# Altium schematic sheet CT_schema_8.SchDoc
size 254 x 194 mm
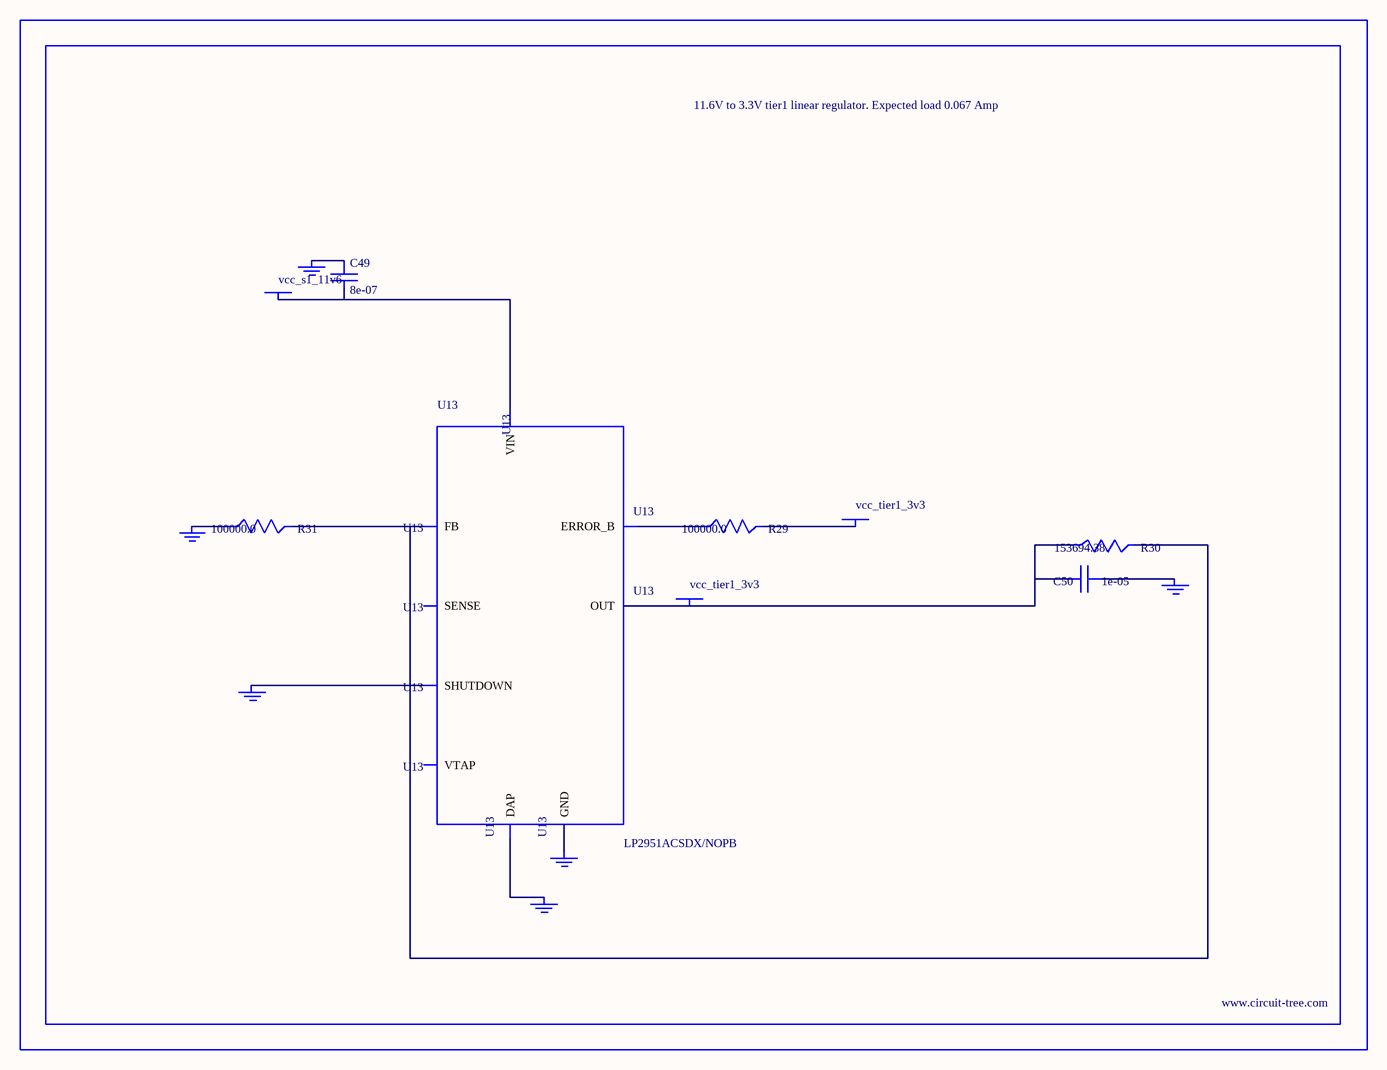
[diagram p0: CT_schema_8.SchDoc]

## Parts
BORDER7  (no value)
C49  8e-07  [R0603]
C50  1e-05  [C1210]
GND_INSTANCE_7_0  (no value)
GND_INSTANCE_7_1  (no value)
GND_INSTANCE_7_2  (no value)
GND_INSTANCE_7_3  (no value)
GND_INSTANCE_7_4  (no value)
GND_INSTANCE_7_5  (no value)
POWER_INSTANCE_7_0  vcc_tier1_3v3
POWER_INSTANCE_7_1  vcc_s1_11v6
POWER_INSTANCE_7_2  vcc_tier1_3v3
R29  100000.0  [R0603]
R30  153694.38  [R0603]
R31  100000.0  [R0603]
U13  LP2951ACSDX/NOPB  [WSON-8]

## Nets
NetC49_1: C49.1 GND_INSTANCE_7_3.0(GND)
NetC49_2: C49.2 POWER_INSTANCE_7_1.0(PWR) U13.8(VIN)
NetC50_1: C50.1 GND_INSTANCE_7_0.0(GND)
NetC50_2: C50.2 POWER_INSTANCE_7_2.0(PWR) R30.1 U13.1(OUT)
NetGND_INSTANCE_7_1_0: GND_INSTANCE_7_1.0(GND) U13.3(SHUTDOWN)
NetGND_INSTANCE_7_2_0: GND_INSTANCE_7_2.0(GND) R31.1
NetGND_INSTANCE_7_4_0: GND_INSTANCE_7_4.0(GND) U13.PAD(DAP)
NetGND_INSTANCE_7_5_0: GND_INSTANCE_7_5.0(GND) U13.4(GND)
NetPOWER_INSTANCE_7_0_0: POWER_INSTANCE_7_0.0(PWR) R29.2
NetR29_1: R29.1 U13.5(ERROR_B)
NetR30_2: R30.2 R31.2 U13.7(FB)

Not connected (* = marked no-connect by the designer): U13 2(SENSE) 6(VTAP)

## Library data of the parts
BORDER7 = BORDER_PAGE7
C49 = C49
C50 = GRM32DR61E106MA12L
GND_INSTANCE_7_0-GND_INSTANCE_7_5 = GND
POWER_INSTANCE_7_0-POWER_INSTANCE_7_2 = PWR
R29 R31 = RC0603JR-07100KL
R30 = R30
